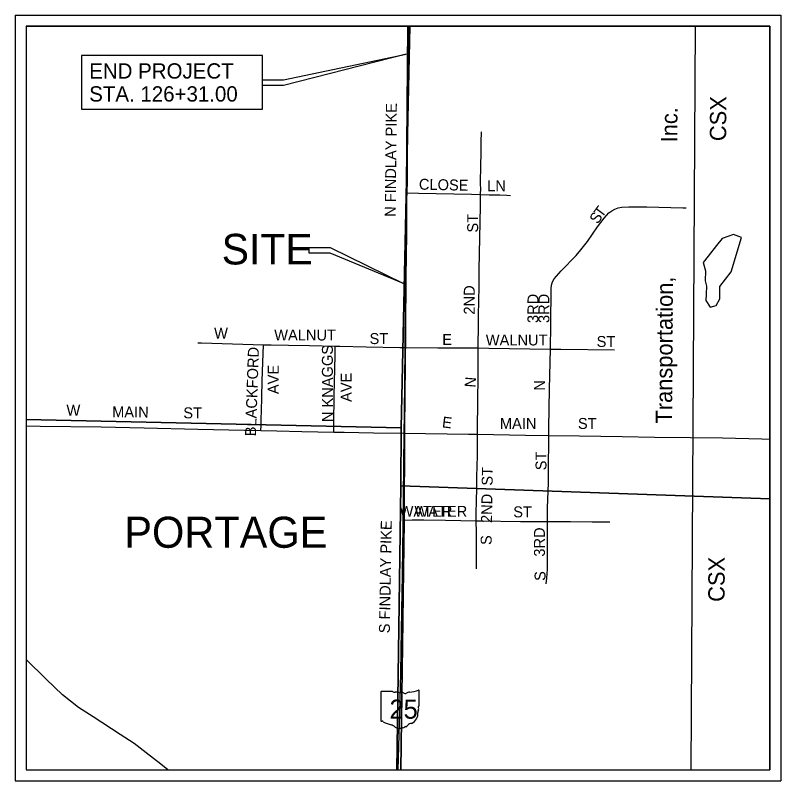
# Model space of a CAD drawing. Extents: x -107 to 120, y -81 to 213.
# Drawn here: x -4.15 to 2.85, y 15.62 to 22.62 of the extents above; entities that cross this region are included whole.
import ezdxf

# ---------------------------------------------------------------- set-up
doc = ezdxf.new("R2010")
doc.units = 0
for name, color, linetype in [('GM_X_City_Street', 7, 'Continuous'), ('GM_X_City_Street_Text', 7, 'Continuous'), ('GM_X_Corporation_Text', 7, 'Continuous'), ('GM_X_Minor_Lake', 7, 'Continuous'), ('GM_X_Minor_River', 7, 'Continuous'), ('GM_X_Rail_Line', 7, 'Continuous'), ('GM_X_Rail_Line_Text', 7, 'Continuous'), ('GM_X_Section', 7, 'Continuous'), ('GM_X_State_Location', 7, 'Continuous'), ('GM_X_State_Route', 7, 'Continuous'), ('GM_X_State_Shield', 7, 'Continuous'), ('GM_X_Township', 7, 'Continuous'), ('SH_Data', 7, 'Continuous'), ('SH_Text', 7, 'Continuous')]:
    doc.layers.add(name, color=color, linetype=linetype)

msp = doc.modelspace()

# ---------------------------------------------------------------- linework, layer by layer
at = {"layer": 'GM_X_City_Street'}
for points in [[(0.1084, 20.9824), (0.1094, 21.0381), (0.1088, 21.0702), (0.1115, 21.266), (0.1124, 21.3412), (0.114, 21.4613), (0.1153, 21.5554)], [(-0.5641, 20.9966), (-0.4611, 20.9938), (-0.2991, 20.9893), (0.0257, 20.9854), (0.1084, 20.9824)], [(0.0863, 19.5776), (0.0869, 19.6471), (0.0876, 19.7339), (0.0886, 19.845), (0.0936, 20.0409), (0.0939, 20.1057), (0.0941, 20.2036), (0.0948, 20.2335), (0.0954, 20.2959), (0.1082, 20.8755), (0.1082, 20.9731), (0.1084, 20.9824)], [(0.1084, 20.9824), (0.1876, 20.9796), (0.2845, 20.9778), (0.3487, 20.9753), (0.3804, 20.9735)], [(0.7462, 19.5673), (0.7506, 19.7923), (0.7538, 20.1197), (0.7559, 20.1524), (0.7646, 20.1837), (0.7819, 20.2112), (0.8035, 20.236), (0.8465, 20.284), (0.9837, 20.4246), (1.0254, 20.4748), (1.0859, 20.5521), (1.1788, 20.687), (1.238, 20.7653), (1.2592, 20.7904), (1.2821, 20.8137), (1.3082, 20.8335), (1.3369, 20.8487), (1.3679, 20.8588), (1.4, 20.8644), (1.4655, 20.8682), (1.6294, 20.8683), (1.9567, 20.86), (1.9894, 20.8596)], [(-2.4767, 19.6252), (-2.4446, 19.6251), (-1.8781, 19.608)], [(-1.9008, 18.8223), (-1.8994, 18.8701), (-1.8977, 18.934), (-1.8958, 19), (-1.8922, 19.1286), (-1.8881, 19.278), (-1.8834, 19.4448), (-1.8781, 19.608)], [(-1.8781, 19.608), (-1.8077, 19.6069), (-1.6479, 19.6044), (-1.4555, 19.6015), (-1.221, 19.5949)], [(-1.2338, 18.8093), (-1.2333, 18.8819), (-1.2313, 19.1459), (-1.223, 19.5088), (-1.221, 19.5949)], [(-1.221, 19.5949), (-1.1788, 19.5944), (-0.9374, 19.5892), (-0.6299, 19.5825), (-0.5802, 19.5814)], [(-0.5802, 19.5814), (-0.2824, 19.5803), (-0.0806, 19.5781), (0.0863, 19.5776)], [(0.081, 18.7886), (0.0809, 18.815), (0.0806, 18.8986), (0.0822, 19.0252), (0.083, 19.0913), (0.0841, 19.1729), (0.0849, 19.2372), (0.0851, 19.3257), (0.0852, 19.4484), (0.0855, 19.4925), (0.0863, 19.5776)], [(0.0863, 19.5776), (0.1831, 19.5773), (0.7462, 19.5673)], [(0.7328, 18.7778), (0.7338, 18.843), (0.7393, 19.2031), (0.7462, 19.5673)], [(0.7462, 19.5673), (0.8426, 19.5656), (1.3327, 19.5612)], [(-4.0471, 18.8643), (-3.9197, 18.8637), (-3.3619, 18.857), (-3.231, 18.8533), (-2.97, 18.8477), (-2.4783, 18.8362), (-2.0517, 18.8263), (-1.9008, 18.8223)], [(-1.9008, 18.8223), (-1.7566, 18.8185), (-1.5267, 18.8144), (-1.2338, 18.8093)], [(-1.2338, 18.8093), (-1.1402, 18.8076), (-0.8703, 18.8029), (-0.5901, 18.8001)], [(-0.5901, 18.8001), (-0.0037, 18.79), (0.081, 18.7886)], [(0.0685, 17.9977), (0.0689, 18.0746), (0.0712, 18.1719), (0.0732, 18.3018), (0.0733, 18.3668), (0.075, 18.3992), (0.0788, 18.5946), (0.081, 18.7886)], [(0.081, 18.7886), (0.5202, 18.7813), (0.7328, 18.7778)], [(0.7189, 17.9906), (0.7196, 18.0237), (0.7214, 18.1149), (0.7281, 18.3442), (0.7294, 18.443), (0.7328, 18.7778)], [(0.7328, 18.7778), (1.0116, 18.7732), (1.4045, 18.7675), (1.6993, 18.7635), (2.0267, 18.7591), (2.3212, 18.7553), (2.6813, 18.7459), (2.7529, 18.7449)], [(-0.5994, 18.0045), (-0.5184, 18.0051), (-0.4102, 18.006), (-0.2141, 18.0023), (0.0685, 17.9977)], [(0.0716, 17.5573), (0.0706, 17.6218), (0.0697, 17.6862), (0.0701, 17.7187), (0.07, 17.9144), (0.069, 17.9731), (0.0685, 17.9977)], [(0.0685, 17.9977), (0.109, 17.997), (0.4731, 17.9911), (0.6342, 17.9908), (0.7189, 17.9906)], [(0.7079, 17.4195), (0.7151, 17.4715), (0.7179, 17.5164), (0.7196, 17.5521), (0.7205, 17.6261), (0.7196, 17.7897), (0.7199, 17.92), (0.7189, 17.9906)], [(0.7189, 17.9906), (0.817, 17.9904), (0.9312, 17.9902), (1.1275, 17.9887), (1.1928, 17.9881), (1.2896, 17.9887)]]:
    msp.add_lwpolyline(points, dxfattribs=at)
at = {"layer": 'GM_X_Minor_Lake'}
msp.add_line((2.1634, 20.1916), (2.1753, 20.1434), dxfattribs=at)
msp.add_lwpolyline([(2.1753, 20.1434), (2.171, 20.0712), (2.1668, 20.0111), (2.2067, 19.9508), (2.2629, 19.9667), (2.2951, 20.0267), (2.2954, 20.1391), (2.4001, 20.2751), (2.4932, 20.5877), (2.4211, 20.616), (2.3169, 20.5802), (2.2646, 20.5162), (2.1881, 20.4162), (2.1439, 20.3601), (2.1637, 20.2839), (2.1634, 20.1916)], dxfattribs=at)
at = {"layer": 'GM_X_Minor_River'}
msp.add_lwpolyline([(-2.751, 15.7203), (-2.8148, 15.7701), (-2.9507, 15.8747), (-3.0586, 15.9593), (-3.1866, 16.0439), (-3.4345, 16.2051), (-3.5704, 16.2897), (-3.7143, 16.4064), (-3.8661, 16.5473), (-4.0471, 16.7296)], dxfattribs=at)
at = {"layer": 'GM_X_Rail_Line'}
msp.add_line((2.0342, 15.7203), (2.0743, 22.5203), dxfattribs=at)
at = {"layer": 'GM_X_Section'}
for points in [[(-0.5384, 22.5203), (-4.0471, 22.5203), (-4.0471, 18.9242), (-0.6191, 18.8485)], [(2.7529, 18.1975), (2.7529, 22.5203), (-0.5384, 22.5203), (-0.6191, 18.8485), (-0.6221, 18.3163)], [(-4.0471, 18.9242), (-4.0471, 15.7203), (-0.6592, 15.7203), (-0.6221, 18.3163), (-0.6191, 18.8485)], [(-0.6592, 15.7203), (2.7529, 15.7203), (2.7529, 18.1975), (-0.6221, 18.3163)]]:
    msp.add_lwpolyline(points, close=True, dxfattribs=at)
at = {"layer": 'GM_X_State_Route'}
msp.add_line((-0.6462, 15.7203), (-0.6284, 16.358), dxfattribs=at)
for points in [[(-0.5673, 20.6164), (-0.5652, 20.9457), (-0.5641, 20.9966), (-0.5617, 21.1095), (-0.5591, 21.3549), (-0.5575, 21.5139), (-0.5562, 21.6351), (-0.5534, 21.8972), (-0.5515, 22.0629), (-0.5494, 22.2564), (-0.547, 22.3826), (-0.5448, 22.458), (-0.5424, 22.5203)], [(-0.5787, 19.7081), (-0.5729, 20.1907), (-0.5691, 20.4529), (-0.5675, 20.5851), (-0.5673, 20.6164)], [(-0.6119, 17.2023), (-0.6099, 17.3244), (-0.6039, 17.7145), (-0.6007, 17.9194), (-0.5994, 18.0045), (-0.5962, 18.2168), (-0.5901, 18.8001), (-0.5872, 18.9766), (-0.5839, 19.2714), (-0.5802, 19.5814), (-0.5787, 19.7081)], [(-0.6284, 16.358), (-0.6214, 16.6082), (-0.6151, 17.0016), (-0.6126, 17.1589), (-0.6119, 17.2023)]]:
    msp.add_lwpolyline(points, dxfattribs=at)
at = {"layer": 'GM_X_State_Shield'}
for p, q in [((-0.8027, 16.4327), (-0.8027, 16.1686)), ((-0.6974, 16.4373), (-0.7993, 16.4373)), ((-0.4547, 16.3057), (-0.4547, 16.4438)), ((-0.4547, 16.3057), (-0.4547, 16.3057))]:
    msp.add_line(p, q, dxfattribs=at)
for centre, radius, start, end in [((-0.7987, 16.4333), 0.00403, 98.1301, 188.1301), ((-0.6731, 16.468), 0.0391, 231.61951, 271.11188), ((-0.6601, 16.289), 0.1404, 80.48669, 94.98827), ((-0.6282, 16.4347), 0.0113, 219.79206, 297.10237), ((-0.6117, 16.4041), 0.0235, 54.46668, 119.14113), ((-0.5814, 16.446), 0.0282, 233.85621, 294.82819), ((-0.5316, 16.3566), 0.0743, 97.34618, 120.76885), ((-0.5786, 16.7974), 0.3691, 275.84447, 288.90645), ((-0.4585, 16.4444), 0.00387, 351.86209, 97.738), ((-0.558, 16.2302), 0.0923, 292.30889, 8.98584), ((-0.4408, 16.2478), 0.0262, 136.8065, 186.92959), ((-0.4556, 16.2955), 0.006, 107.94398, 210.33697), ((-0.4937, 16.278), 0.036, 340.03296, 23.64957), ((-0.4588, 16.3051), 0.00415, 289.60381, 7.73413), ((-0.7987, 16.168), 0.00407, 171.95839, 258.30661), ((-0.7981, 16.195), 0.031, 267.33899, 280.60386), ((-0.7917, 16.1534), 0.0112, 29.74838, 93.27175), ((-0.6504, 16.3907), 0.2665, 240.41292, 257.1985), ((-0.7299, 16.0499), 0.0834, 47.18416, 75.83597), ((-0.6397, 16.152), 0.0529, 230.70037, 286.29184), ((-0.6091, 16.0607), 0.0435, 85.69512, 111.20995), ((-0.6052, 16.1323), 0.0282, 268.77702, 315.54927), ((-0.5797, 16.1067), 0.00794, 65.75173, 132.64842), ((-0.5831, 16.143), 0.0298, 282.87319, 323.27711), ((-0.519, 16.0944), 0.0506, 94.40312, 142.57675)]:
    msp.add_arc(centre, radius, start, end, dxfattribs=at)
at = {"layer": 'GM_X_Township'}
for points in [[(-0.5576, 22.5203), (-4.0471, 22.5203), (-4.0471, 15.7203), (-0.6225, 15.7203), (-0.5918, 17.9957), (-0.5869, 18.7948), (-0.5818, 19.5847)], [(-0.6225, 15.7203), (2.7529, 15.7203), (2.7529, 22.5203), (-0.5576, 22.5203), (-0.5818, 19.5847), (-0.5869, 18.7948), (-0.5918, 17.9957)]]:
    msp.add_lwpolyline(points, close=True, dxfattribs=at)
at = {"layer": 'SH_Data'}
for p, q in [((-4.1471, 22.6203), (2.8529, 22.6203)), ((-4.1471, 22.6203), (-4.1471, 15.6203)), ((2.8529, 22.6203), (2.8529, 15.6203)), ((-4.0471, 22.5203), (-4.0471, 15.7203)), ((-4.0471, 22.5203), (2.7529, 22.5203)), ((-4.0471, 22.5203), (-4.0471, 15.7203)), ((-4.0471, 22.5203), (2.7529, 22.5203)), ((2.7529, 22.5203), (2.7529, 15.7203)), ((2.7529, 22.5203), (2.7529, 15.7203)), ((-4.0471, 15.7203), (2.7529, 15.7203)), ((-4.0471, 15.7203), (-4.0471, 15.7203)), ((-4.0471, 15.7203), (2.7529, 15.7203)), ((-4.0471, 15.7203), (-4.0471, 15.7203)), ((-4.1471, 15.6203), (2.8529, 15.6203))]:
    msp.add_line(p, q, dxfattribs=at)
msp.add_lwpolyline([(-0.5603, 22.265), (-0.5828, 19.3636), (-0.5874, 19.0367), (-0.6208, 16.6482)], dxfattribs=at)
at = {"layer": 'SH_Text'}
for p, q in [((-1.6957, 22.0293), (-0.5733, 22.2642)), ((-0.5733, 22.2642), (-1.6957, 21.9769)), ((-1.8864, 21.9769), (-1.8864, 22.0293)), ((-1.8864, 22.0293), (-1.6957, 22.0293)), ((-1.6957, 21.9769), (-1.8864, 21.9769)), ((-1.4597, 20.4436), (-1.4597, 20.4961)), ((-1.4597, 20.4961), (-1.2689, 20.4961)), ((-1.2689, 20.4436), (-1.4597, 20.4436)), ((-1.2689, 20.4961), (-0.5974, 20.1668)), ((-0.5974, 20.1668), (-1.2689, 20.4436))]:
    msp.add_line(p, q, dxfattribs=at)
msp.add_lwpolyline([(-3.5412, 21.7614), (-1.8864, 21.7614), (-1.8864, 22.2514), (-3.5412, 22.2514)], close=True, dxfattribs=at)

# ---------------------------------------------------------------- texts
at = {"layer": 'GM_X_City_Street_Text'}
for s, rotation, p in [('N FINDLAY PIKE', 89.40143, (-0.6684, 20.7765)), ('CLOSE', 358.66292, (-0.4567, 21.0261)), ('LN', 0.00001, (0.1687, 21.0112)), ('T', 53.41422, (1.2175, 20.7622)), ('ST', 90, (0.0859, 20.6332)), ('S', 56.77222, (1.1799, 20.7046)), ('2ND', 90, (0.0547, 19.8833)), ('3RD', 90, (0.6371, 19.8059)), ('3RD', 90, (0.7371, 19.8059)), ('W', 0.00001, (-2.3288, 19.6626)), ('WALNUT', 0.00001, (-1.7792, 19.6462)), ('ST', 0.00001, (-0.9073, 19.6136)), ('E', 0.00001, (-0.2422, 19.605)), ('WALNUT', 0.00001, (0.1558, 19.601)), ('ST', 0.00001, (1.1695, 19.5872)), ('BLACKFORD', 88.04434, (-1.9464, 18.7689)), ('N KNAGGS', 90, (-1.2429, 18.8995)), ('AVE', 90, (-1.7377, 19.1556)), ('AVE', 90, (-1.0709, 19.0843)), ('N', 85.07664, (0.0604, 19.213)), ('N', 90, (0.6965, 19.1873)), ('W', 0.00001, (-3.6791, 18.9581)), ('MAIN', 359.72969, (-3.2617, 18.9433)), ('ST', 0.00001, (-2.6106, 18.9344)), ('E', 352.88171, (-0.2483, 18.8523)), ('MAIN', 0.00001, (0.2848, 18.8376)), ('ST', 0.00001, (0.9984, 18.8376)), ('ST', 90, (0.7107, 18.4596)), ('S   2ND  ST', 89.01399, (0.2085, 17.7754)), ('WATER', 0.00001, (-0.6326, 18.0337)), ('WATER', 0.00001, (-0.4964, 18.0337)), ('ST', 0.00001, (0.4066, 18.0287)), ('S FINDLAY PIKE', 88.98901, (-0.722, 16.9679)), ('3RD', 90, (0.6965, 17.6693)), ('S', 90, (0.7019, 17.4476))]:
    msp.add_text(s, height=0.1, rotation=rotation, dxfattribs=at).set_placement(p)
at = {"layer": 'GM_X_Corporation_Text'}
msp.add_text('PORTAGE', height=0.28409, rotation=0.00001, dxfattribs=at).set_placement((-3.1504, 17.7505))
at = {"layer": 'GM_X_Rail_Line_Text'}
for s, rotation, p in [('CSX', 89.46978, (2.3535, 21.469)), ('Inc.', 89.66315, (1.9078, 21.4578)), ('Transportation,', 89.66381, (1.8596, 18.886)), ('CSX', 89.73488, (2.3396, 17.2557))]:
    msp.add_text(s, height=0.1495, rotation=rotation, dxfattribs=at).set_placement(p)
at = {"layer": 'GM_X_State_Location'}
for s in ['s', 'r']:
    msp.add_text(s, height=0.002, dxfattribs=at).set_placement((-0.6237, 16.1793))
msp.add_text('25', height=0.001, rotation=0.00001, dxfattribs=at).set_placement((-0.5249, 16.1682))
at = {"layer": 'GM_X_State_Shield'}
msp.add_text('25', height=0.17402, dxfattribs=at).set_placement((-0.7254, 16.1872))
at = {"layer": 'SH_Text'}
for s, height, p in [('END PROJECT', 0.14, (-3.4712, 22.0414)), ('STA. 126+31.00', 0.14, (-3.4712, 21.8314)), ('SITE', 0.28, (-2.2598, 20.3416))]:
    msp.add_text(s, height=height, dxfattribs=at).set_placement(p)

doc.saveas('drawing.dxf')
